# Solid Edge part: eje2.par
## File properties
Author: there
Template: iso metric part.par
Last saved by: there
Revision: 9
Application: Solid Edge
Precisión: 0.990
Username: there
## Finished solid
Body 1: solid body, 3 faces, 2 edges, 0 vertices.
  Faces by surface: plane 2, cylinder 1
  Edges by curve: circle 2
Bounding box of the edges (mm): 6.400 x 120.000 x 6.400, from (-3.2, -40, -3.2) to (3.2, 80, 3.2).
Cylindrical faces by radius (mm): R3.2 x1
Planar faces by outward normal: +y 1, -y 1
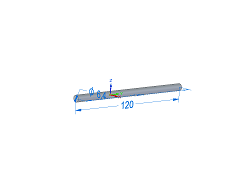
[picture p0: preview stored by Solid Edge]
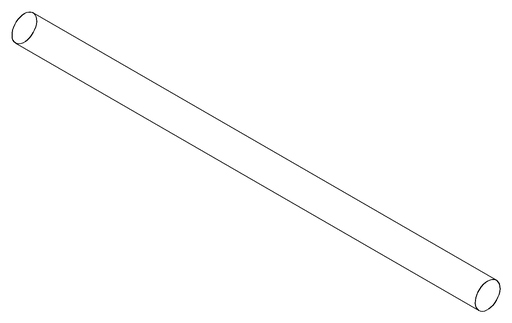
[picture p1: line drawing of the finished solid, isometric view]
